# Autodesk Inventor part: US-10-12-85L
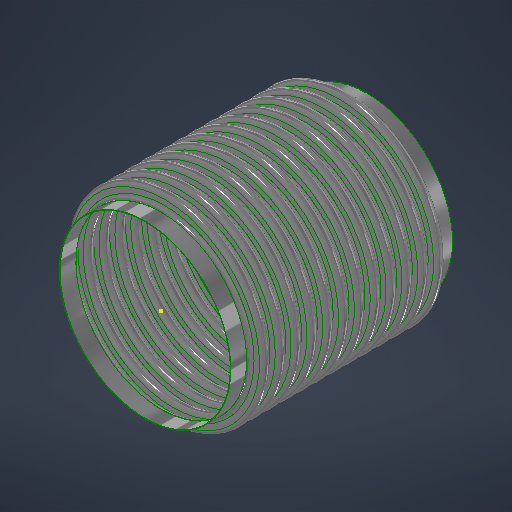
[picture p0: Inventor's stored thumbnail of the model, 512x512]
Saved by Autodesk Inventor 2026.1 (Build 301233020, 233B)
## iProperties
Category: 20 GA (0.036 THICK)
RuleStatus: InUse
Created: 2026-07
Part Number: US-10-12-85L
Project: =STOCK BELLOWS: <Stock Number><SFILL>
Material: ASTM A240-304
Description: =STOCK BELLOWS: <Stock Number>, <SID_> I.D., <SOD_> O.D., <SPLY_> PLY, <Category>, <SNET_CONS> CONS.<PITCH_><STANGENT_> TANGENT<SFILL>
Document SubType Name: Sheet Metal
Designer: LC
Stock Number: U.S-10-12-85L
Surface Area: 659.127 cm^2
Volume: 56.61 cm^3
Sheet Metal Rule: Default
Appearance: STAINLESS STEEL
NET_TUBE: 3.428
COUNTER: 1.500
PBAR: 1.214
PSET: 5.356
PLY: 2
CONS: 2
THK: 0.036
ID: 4.500
OD: 5.500
CONS_: 2
TANGENT: 0.500
PITCH: 0.375
BELLOWS_UPSET: 0.000
NET_CONS: 2
S_CONS: 0
Description_Units: 0
ID_M: 114.30 mm
OD_M: 139.70 mm
THK_M: 0.91 mm
ID_U: 4.500 in
OD_U: 5.500 in
THK_U: 0.036 in
TANGENT2: 0.500
d79: 1.000
d82: 1.000
d83: 26.000
d84: 24.000
d80: 2.571
d81: 10
SID: 2.375
SCONS_: 12
SPITCH: 0.250
SBELLOWS_UPSET: 0.000
SNET_CONS: 12
SS_CONS: 0
SCONS: 8
d174: 8
d177: 0.018
d178: 2.375
d179: 3.000
d180: 0.375
d181: 1.000
d182: 0.000
d190: 8
d191: 1
d192: 1
d193: 8
d194: 0
PART_NUMBER: U.S-10-12-85L
PRESSURE: 85
SIZE: 10.00
STANGENT_: 1.000
d214: 8
d217: 0.030
d218: 6.625
d219: 8.125
d220: 0.500
d221: 1.000
d222: 0.000
d230: 8
d231: 1
d232: 1
d233: 8
d234: 0
STANGENT: 4.000
SPLY_: 1
STHK_: 0.036
SID_: 10.750
SOD_: 12.500
SPITCH_: 1.000
STANGENT__: 1.000
SBELLOWS_UPSET_: 0.000
SDIFF_TAN: 1.000
TAN_TO_TAN: 0.750 in
d252: 2
d275: 2
d287: 0.050
d289: 0.500
d290: 0.000
d263: 2
d265: 1
d268: 2
d269: 0
d286: 2
d288: 1
d291: 2
d292: 0
SOD_NECK: 10 13/16
CFILL: .
SFILL: .
PITCH_: =, <SPITCH_> PITCH,
SREROLL: 0.750
MATTABLE: 20 GA (0.036 THICK)
MESH: ,
CSECT: 2
Author: LC
Keywords: 20 GA (0.036 THICK)
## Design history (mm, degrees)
sketch "Sketch2"
  geometry: L1 (0, -183.595)-(0, 600.956) reference; L2 (58.979, 0)-(57.15, 0); L3 (60.446, -1.467)-(66.554, -1.467); L4 (60.446, -3.296)-(66.554, -3.296); L5 (66.554, -8.058)-(60.446, -8.058); L6 (66.554, -6.229)-(60.446, -6.229); L7 (58.979, -9.525)-(57.15, -9.525); L8 (60.446, 0)-(60.446, -9.525); L9 (66.554, -4.762)-(69.85, -4.763); L10 (57.15, 0)-(57.15, -9.525); L11 (20.376, 102.841)-(20.376, 101.926); L12 (58.262, 488.877)-(58.262, 349.177); L13 (58.262, 479.352)-(58.262, 339.652); L14 (93.133, -58.817)-(93.133, -71.517); L15 (118.746, -66.401)-(118.746, -66.401); L16 (66.554, -6.229)-(66.554, -8.058); L17 (60.446, -6.229)-(60.446, -8.058); L18 (60.446, -7.144)-(66.554, -7.144); L19 (69.85, 0)-(69.85, -9.525); L20 (-66.554, -6.229)-(-66.554, -8.058); L21 (-66.554, -1.467)-(-60.446, -1.467); L22 (-66.554, -3.296)-(-60.446, -3.296); L23 (-60.446, -6.229)-(-66.554, -6.229); L24 (-66.554, -7.144)-(-60.446, -7.144); L25 (-60.446, -8.058)-(-66.554, -8.058); L26 (-60.446, -6.229)-(-60.446, -8.058); L27 (-57.15, -2.522)-(-57.15, -12.047); L28 (-60.446, -4.763)-(-57.15, -4.763); L29 (-66.554, 3.828)-(-66.554, -9.525); L30 (-68.021, 0)-(-69.85, 0); L31 (-69.85, 0)-(-69.85, -9.525); L32 (-68.021, -9.525)-(-69.85, -9.525); A1 r 1.467 centre (60.446, 0) between (58.979, 0) and (60.446, -1.467); A2 r 3.296 centre (60.446, 0) between (57.15, 0) and (60.446, -3.296); A3 r 3.296 centre (66.554, -4.762) between (66.554, -8.058) and (66.554, -1.467); A4 r 1.467 centre (66.554, -4.762) between (66.554, -6.229) and (66.554, -3.296); A5 r 1.467 centre (60.446, -9.525) between (60.446, -8.058) and (58.979, -9.525); A6 r 3.296 centre (60.446, -9.525) between (60.446, -6.229) and (57.15, -9.525); A7 r 2.381 centre (66.554, -4.762) between (66.554, -7.144) and (68.936, -4.762); A8 r 2.381 centre (60.446, -9.525) between (60.446, -7.144) and (58.064, -9.525); A9 r 1.467 centre (-66.554, -9.525) between (-66.554, -8.058) and (-68.021, -9.525); A10 r 1.467 centre (-60.446, -4.763) between (-60.446, -6.229) and (-60.446, -3.296); A11 r 2.381 centre (-60.446, -4.763) between (-60.446, -7.144) and (-58.064, -4.763); A12 r 3.296 centre (-60.446, -4.763) between (-60.446, -8.058) and (-60.446, -1.467); A13 r 2.381 centre (-66.554, -9.525) between (-66.554, -7.144) and (-68.936, -9.525); A14 r 3.296 centre (-66.554, -9.525) between (-66.554, -6.229) and (-69.85, -9.525); A15 r 1.467 centre (-66.554, 0) between (-68.021, 0) and (-66.554, -1.467); A16 r 3.296 centre (-66.554, 0) between (-69.85, 0) and (-66.554, -3.296); 10 further points
  constraints: 62 end point, 38 point on circle, 20 tangent, 16 centre point, 12 parallel, 9 midpoint, 7 vertical, 6 coincident, 6 concentric, 6 point on line, 4 equal radius, 4 perpendicular, 3 horizontal, 1 collinear, 1 horizontal alignment, 10 other
  dimensions: "THK" = 0.9144 distance of L11.start L11.end; "ID" = 114.3 distance of L11.end point (20.376, -12.374); "OD" = 139.7 distance of L12.start L12.end; "PITCH" = 9.525 distance of L12.start L13.start; "TANGENT" = 12.7 distance of L14.start L14.end; "BELLOWS_UPSET" = 0 distance of L15.start L15.end; "d43" = 114.3 diameter of L10 L1 (= ID); "d44" = 139.7 diameter of L9.end L1 (= OD); "d45" = 1.8288 distance between parallel lines of L5 L6 (computed from THK, PLY); "d46" = 3.29565 radius of A3 (computed from PITCH, THK, PLY); "UPSET_PITCH" = 9.525 distance of L2.end L7.end (derived); "SIDEWALL_ANGLE" = 0 deg angle of L3 L9 (derived); "CON_GAP" = 2.9337 distance of point (60.446, -6.229) point (60.446, -3.296) (derived); "TAN1" = 3.74046 dimension on A8 (derived); "TAN2" = 3.74046 dimension on A7 (derived); "LEG1" = 6.1087 distance of L18.start L18.end (derived); "d278" = 1.8288 distance between parallel lines of L25 L23 (derived); "d279" = 3.29565 radius of A12 (derived); "d280" = 9.525 distance of L30.end L31.end (derived); "d281" = 360 deg dimension on L21 L28 (derived); "d282" = 2.9337 distance of point (-66.554, -6.229) point (-66.554, -3.296) (derived); "d283" = 3.74046 dimension on A13 (derived); "d284" = 3.74046 dimension on A11 (derived); "d285" = 6.1087 distance of L24.start L24.end (derived); "d293" = 114.3 diameter of L27 L1 (derived); "d294" = 139.7 diameter of L31 L1 (derived)
  node "Sketch Rectangular Pattern1" dims "d31" = 25.4, "ID" = 114.3
  node "Sketch Rectangular Pattern2" dims "d39" = 25.4, "PITCH" = 9.525
revolve "CONS" stored, may be unused: angle "d48" = 90 deg
node "BELLOW MIDPLANE"
pattern_linear "Rectangular Pattern2" dims "d52" = 9.525 (= UPSET_PITCH)
sketch "Sketch5"
  geometry: C1 r 58.979 at (0, 0) reference; C2 r 57.15 at (0, 0) reference
extrude "TANGENT" new body sketch "Sketch5" distance "d53" = 12.7 (= TANGENT); taper "d54" = 0 deg
revolve "SAMETAN" stored, may be unused: angle "d65" = 90 deg
revolve "DIFFTAN" stored, may be unused: angle "d70" = 90 deg
sketch "Sketch9"
  geometry: L1 (58.391, 0)-(-58.391, 0) reference; L2 (0, -17.78)-(0, 17.78) reference; L3 (41.708, 0)-(-41.708, 0); L4 (41.708, -11.906)-(41.708, 11.906); L5 (29.008, -11.906)-(29.008, 11.906); L6 (15.418, 11.906)-(15.418, -11.906); L7 (-29.008, -11.906)-(-29.008, 11.906); L8 (-41.708, -11.906)-(-41.708, 11.906); L9 (40.914, -11.906)-(40.914, 11.906); L10 (41.708, -11.906)-(40.914, -11.906); L11 (41.708, 11.906)-(40.914, 11.906); L12 (15.815, 11.906)-(15.022, 11.906); L13 (15.022, 11.906)-(15.022, -11.906); L14 (15.022, -11.906)-(15.815, -11.906); L15 (15.815, -11.906)-(15.815, 11.906); L16 (-15.815, 11.906)-(-15.815, -11.906); L17 (-15.418, 11.906)-(-15.418, -11.906); L18 (-15.815, -11.906)-(-15.022, -11.906); L19 (-15.022, -11.906)-(-15.022, 11.906); L20 (-15.022, 11.906)-(-15.815, 11.906); L21 (-41.708, -11.906)-(-40.914, -11.906); L22 (-40.914, -11.906)-(-40.914, 11.906); L23 (-40.914, 11.906)-(-41.708, 11.906); L24 (-41.708, 11.906)-(-41.708, -11.906); L25 (41.708, -0.397)-(-41.708, -0.397); L26 (-41.708, -0.397)-(-41.708, 0.397); L27 (-41.708, 0.397)-(41.708, 0.397); L28 (41.708, 0.397)-(41.708, -0.397); L29 (-41.708, 11.906)-(41.708, 11.906); L30 (41.708, 11.906)-(41.708, 12.7); L31 (41.708, 12.7)-(-41.708, 12.7); L32 (-41.708, 12.7)-(-41.708, 11.906); L33 (41.708, -11.906)-(-41.708, -11.906); L34 (-41.708, -11.906)-(-41.708, -12.7); L35 (-41.708, -12.7)-(41.708, -12.7); L36 (41.708, -12.7)-(41.708, -11.906); 30 further points
  constraints: 68 end point, 13 midpoint, 13 parallel, 8 horizontal, 7 perpendicular, 6 equal length, 3 point on line, 2 vertical, 14 other
  dimensions: "d115" = 23.8125 distance of L4.start L4.end (derived); "d116" = 12.7 distance between parallel lines of L4 L5 (derived); "d117" = 13.58962 distance between parallel lines of L5 L6 (derived); "d125" = 44.42645 distance between parallel lines of L7 L6 (derived); "d127" = 12.7 distance between parallel lines of L8 L7 (derived); "d128" = 26.28962 distance between parallel lines of L6 L4 (derived); "d130" = 83.41607 distance between parallel lines of L8 L4 (derived); "RULER_THK" = 0.79375 distance between parallel lines of L4 L9; "d135" = 0.79375 distance of L13.end L14.end (derived); "d138" = 30.83684 distance of L13.end L16.end (derived); "d143" = 0.79375 distance of L22.end L8.end (derived); "d144" = 0.79375 distance between parallel lines of L27 L25 (derived)
extrude "RULER" join sketch "Sketch9" distance "d149" = 0.79375 (derived); taper "d150" = 0 deg
extrude "BARS" join sketch "Sketch9" distance "d151" = 0.79375 (derived); taper "d152" = 0 deg
pattern_linear "Rectangular Pattern4" dims "d155" = 30.83684 (derived)
sketch "Sketch13"
  geometry: L1 (93.149, -52.467)-(93.149, -77.867); L2 (137.439, 0)-(136.525, 0); L3 (137.439, -25.4)-(136.525, -25.4); L4 (151.943, -19.507)-(143.332, -19.507); L5 (151.943, -18.593)-(143.332, -18.593); L6 (151.943, -12.7)-(158.75, -12.7); L7 (143.332, -5.893)-(151.943, -5.893); L8 (143.332, 0)-(143.332, -25.4); L9 (136.525, 0)-(136.525, -25.4); L10 (58.254, -287.939)-(58.254, -605.439); L11 (58.254, -313.339)-(58.254, -630.839); L12 (58.254, -364.139)-(58.254, -681.639); L13 (58.254, -389.539)-(58.254, -707.039); L14 (58.254, -414.939)-(58.254, -732.439); L15 (58.254, -440.339)-(58.254, -757.839); L16 (58.254, -465.739)-(58.254, -783.239); L17 (58.254, -338.739)-(58.254, -656.239); L18 (20.376, 102.841)-(20.376, 101.926); L19 (143.332, -6.807)-(151.943, -6.807); L20 (0, -810.565)-(0, 254.897) reference; L21 (-25.718, 0)-(154.305, 0) reference; A1 r 5.893 centre (143.332, 0) between (137.439, 0) and (143.332, -5.893); A2 r 5.893 centre (143.332, -25.4) between (143.332, -19.507) and (137.439, -25.4); A3 r 6.807 centre (143.332, -25.4) between (143.332, -18.593) and (136.525, -25.4); A4 r 5.893 centre (151.943, -12.7) between (151.943, -18.593) and (151.943, -6.807); A5 r 6.807 centre (151.943, -12.7) between (151.943, -19.507) and (151.943, -5.893); A6 r 6.807 centre (143.332, 0) between (136.525, 0) and (143.332, -6.807); 6 further points; 1 other entity
  constraints: 38 end point, 15 point on circle, 9 tangent, 6 centre point, 6 parallel, 5 vertical alignment, 4 point on line, 4 vertical, 3 coincident, 3 concentric, 2 collinear, 2 equal radius, 1 horizontal, 1 perpendicular, 23 other
  dimensions: "SBELLOWS_UPSET_" = 0 distance of point (118.762, -66.401) point (118.762, -66.401); "STOTAL_THK_BELLOW__" = 0.9144 distance between parallel lines of L4 L5 (derived); "d224" = 6.8072 radius of A5 (derived); "d225" = 25.4 distance of L2.end L3.end (derived); "SSIDEWALL_ANGLE_" = 0 deg angle of L7 L6 (derived); "SSCON_GAP_" = 11.7856 distance of point (143.332, -18.593) point (143.332, -6.807) (derived); "d235" = 273.05 diameter of L9 L20 (derived); "d236" = 317.5 diameter of L6.end L20 (derived)
  node "Sketch Rectangular Pattern4" dims "d228" = 25.4
  node "Sketch Rectangular Pattern5" dims "d229" = 25.4
revolve "SBELLOW" stored, may be unused: angle "d197" = 90 deg
pattern_linear "Rectangular Pattern5" dims "d204" = 25.4 (derived)
revolve "STANGENT" stored, may be unused: angle "d240" = 90 deg
revolve "SSAMETAN" stored, may be unused: angle "d241" = 90 deg
revolve "SDIFFTAN" stored, may be unused: angle "d246" = 90 deg
revolve "INVCON" stored, may be unused: angle "d295" = 90 deg
pattern_linear "Rectangular Pattern6" dims "d298" = 9.525 (derived)
revolve "INVTANGENT" stored, may be unused: angle "d302" = 90 deg
revolve "INVSAMETAN" stored, may be unused: angle "d307" = 90 deg
revolve "INVDIFFTAN" stored, may be unused: angle "d312" = 90 deg
sketch "ID BELLOW MOUNT CALC"
  geometry: L1 (44.45, 0)-(38.1, 0); L2 (38.1, 0)-(38.1, 12.7); L3 (38.1, 12.7)-(44.45, 12.7); L4 (44.45, 12.7)-(44.45, 0); L5 (36.513, 12.7)-(34.684, 12.7); L6 (34.684, 12.7)-(34.684, 0); L7 (34.684, 0)-(36.513, 0); L8 (36.513, 0)-(36.513, 12.7); L9 (0, -2.54)-(0, 15.24) reference; L10 (-8.89, 0)-(53.34, 0) reference; 1 further point
  constraints: 16 end point, 5 parallel, 2 collinear, 2 horizontal, 2 perpendicular
  dimensions: "d314" = 12.7 distance of L5.end L6.end (derived); "d315" = 1.8288 distance of L5.start L5.end (derived); "IG" = 1.5875 distance between parallel lines of L2 L8; "PIPE_OD" = 88.9 diameter of L4 L9; "PIPE_WALL" = 6.35 distance of L2.end L3.end; "ID_MT_BELLOW" = 69.3674 diameter of L6 L9 (derived)
revolve "CFILL" stored, may be unused: angle "d320" = 90 deg
pattern_linear "Rectangular Pattern7" dims "d323" = 9.525 (derived)
revolve "SFILL" stored, may be unused: angle "d324" = 90 deg
pattern_linear "Rectangular Pattern8" dims "d327" = 25.4 (derived)
node "STOCK BELLOW MIDPLANE"
sketch "Sketch21"
  geometry: L1 (0, -222.25)-(0, 222.25) reference; L2 (-222.25, 0)-(222.25, 0) reference; L3 (-0.099, 71.437)-(0.099, 71.437); L4 (0.099, 71.437)-(0.099, 55.562); L5 (0.099, 55.562)-(-0.099, 55.562); L6 (-0.099, 55.562)-(-0.099, 71.437); C1 r 55.562 at (0, 0); C2 r 71.437 at (0, 0); 3 further points
  constraints: 8 end point, 2 centre point, 2 coincident, 2 parallel, 2 tangent, 1 horizontal, 1 perpendicular, 1 other
  dimensions: "d329" = 111.125 diameter of C1 (derived); "d330" = 142.875 diameter of C2 (derived); "d331" = 0.19844 distance of L3.start L3.end
extrude "CLAMSHELL" cut sketch "Sketch21" extent not by distance; stored distance "d332" = 0; taper "d333" = 0 deg
pattern_circular "Circular Pattern1" dims angle "d335" = 180 deg (derived)
node "BELLOW"
sketch "Sketch6"
  geometry: L1 (-19.05, 58.979)-(-6.35, 58.979); L2 (-6.35, 58.979)-(-6.35, 57.15); L3 (-6.35, 57.15)-(-19.05, 57.15); L4 (-19.05, 57.15)-(-19.05, 58.979); L5 (2.54, 0)-(-59.69, 0) reference; L6 (-38.1, -108.388)-(-38.1, 156.601) reference; 1 further point
  constraints: 8 end point, 2 parallel, 1 horizontal, 1 perpendicular
  dimensions: "d61" = 12.7 distance of L2.end L3.end (derived); "d62" = 1.8288 distance of L1.end L2.end (derived); "d63" = 114.3 diameter of L3 L5 (derived); "d64" = 19.05 distance between parallel lines of L4 L6 (derived)
sketch "Sketch12"
  geometry: 1 further point
sketch "Sketch14"
  geometry: L1 (-25.4, 137.439)-(0, 137.439); L2 (0, 137.439)-(0, 136.525); L3 (0, 136.525)-(-25.4, 136.525); L4 (-25.4, 136.525)-(-25.4, 137.439); L5 (5.08, 0)-(-30.48, 0) reference; L6 (0, -22.06)-(0, 132.359) reference; 1 further point
  constraints: 8 end point, 2 parallel, 1 collinear, 1 horizontal, 1 perpendicular
  dimensions: "d237" = 0.9144 distance of L3.end L1.start (derived); "d238" = 273.05 diameter of L3 L5 (derived); "d239" = 25.4 distance of L1.start L1.end (derived); "SOD_NECK" = 274.8788 diameter of L1 L5 (derived)
sketch "Sketch15"
  geometry: L1 (-22.06, 0)-(132.359, 0) reference; L2 (136.525, -304.8)-(137.439, -304.8); L3 (137.439, -304.8)-(137.439, -330.2); L4 (137.439, -330.2)-(136.525, -330.2); L5 (136.525, -330.2)-(136.525, -304.8); L6 (0, -215.9)-(0, 50.8) reference; 1 further point
  constraints: 8 end point, 2 parallel, 1 horizontal, 1 perpendicular
  dimensions: "d205" = 25.4 distance of L4.end L2.start (derived); "d206" = 0.9144 distance of L3.end L4.end (derived); "d207" = 273.05 diameter of L5 L6 (derived); "d208" = 304.8 distance between parallel lines of L1 L2 (derived)
node "TANGENT_"
node "SAME_TAN"
sketch "Sketch8"
  geometry: L1 (58.979, -19.05)-(57.15, -19.05); L2 (57.15, -19.05)-(57.15, -31.75); L3 (57.15, -31.75)-(58.979, -31.75); L4 (58.979, -31.75)-(58.979, -19.05); L5 (0, -40.64)-(0, 21.59) reference; L6 (-108.388, 0)-(156.601, 0) reference; 1 further point
  constraints: 8 end point, 2 parallel, 1 horizontal, 1 perpendicular
  dimensions: "d66" = 114.3 diameter of L2 L5 (derived); "TOTAL_THK_BELLOW" = 1.8288 distance of L2.end L3.end (derived); "d68" = 19.05 distance between parallel lines of L1 L6 (derived); "d69" = 12.7 distance of L1.end L2.end (derived)
node "DIFF_TAN"
node "Sketch Rectangular Pattern3" dims "d138" = 30.83684 (derived), "d141" = 25.4
node "SBELLOW_"
node "STANGENT_"
node "SSAME_TAN"
sketch "Sketch16"
  geometry: L1 (137.439, -304.8)-(136.525, -304.8); L2 (136.525, -304.8)-(136.525, -330.2); L3 (136.525, -330.2)-(137.439, -330.2); L4 (137.439, -330.2)-(137.439, -304.8); L5 (0, -215.9)-(0, 50.8) reference; L6 (-22.06, 0)-(132.359, 0) reference; 1 further point
  constraints: 8 end point, 2 parallel, 1 horizontal, 1 perpendicular
  dimensions: "SDIFF_TAN" = 25.4 distance of L3.end L1.start; "d243" = 0.9144 distance of L2.end L3.end (derived); "d244" = 304.8 distance between parallel lines of L1 L6 (derived); "d245" = 273.05 diameter of L2 L5 (derived)
node "SDIFF_TAN"
body "Solid15"
sketch "Sketch17"
  geometry: L1 (69.85, 12.7)-(68.021, 12.7); L2 (68.021, 12.7)-(68.021, 0); L3 (68.021, 0)-(69.85, 0); L4 (69.85, 0)-(69.85, 12.7); L5 (0, -2.54)-(0, 15.24) reference; L6 (-13.97, 0)-(83.82, 0) reference; 2 further points
  constraints: 8 end point, 2 parallel, 1 horizontal, 1 midpoint, 1 perpendicular, 1 point on line
  dimensions: "INVTANGENT" = 12.7 distance of L3.end L1.start (derived); "d300" = 1.8288 distance of L1.start L1.end (derived); "d301" = 139.7 diameter of L4 L5 (derived)
body "Solid16"
sketch "Sketch18"
  geometry: L1 (69.85, -19.05)-(68.021, -19.05); L2 (68.021, -19.05)-(68.021, -31.75); L3 (68.021, -31.75)-(69.85, -31.75); L4 (69.85, -31.75)-(69.85, -19.05); L5 (-13.97, 0)-(83.82, 0) reference; L6 (0, -40.64)-(0, 21.59) reference; 1 further point
  constraints: 8 end point, 2 parallel, 1 horizontal, 1 perpendicular
  dimensions: "d303" = 19.05 distance between parallel lines of L1 L5 (derived); "d304" = 12.7 distance of L3.end L1.start (derived); "d305" = 1.8288 distance of L2.end L3.end (derived); "d306" = 139.7 diameter of L4 L6 (derived)
body "Solid17"
sketch "Sketch19"
  geometry: L1 (69.85, -19.05)-(68.021, -19.05); L2 (68.021, -19.05)-(68.021, -31.75); L3 (68.021, -31.75)-(69.85, -31.75); L4 (69.85, -31.75)-(69.85, -19.05); L5 (0, -40.64)-(0, 21.59) reference; L6 (-13.97, 0)-(83.82, 0) reference; 1 further point
  constraints: 8 end point, 2 parallel, 1 horizontal, 1 perpendicular
  dimensions: "d308" = 12.7 distance of L1.end L2.end (derived); "d309" = 139.7 diameter of L4 L5 (derived); "d310" = 1.8288 distance of L2.end L3.end (derived); "d311" = 19.05 distance between parallel lines of L1 L6 (derived)
body "Solid18"
body "Solid19"
body "Solid20"
other parameters: "BMPL" = -152.4, "PSET" = 136.0424 (computed from OD, THK, PLY) [user parameter], "PBAR" = 30.83684 (= 0.570796 x PITCH + OD - ID) [user parameter; used in 1 equation term], "COUNTER" = 15 [user parameter], "NET_TUBE" = 87.07367 (computed from CONS_, PBAR, TANGENT) [user parameter], "S_CONS" = 0 [user parameter; used in 1 equation term], "ID_M" = 114.3 (= ID) [user parameter], "OD_M" = 139.7 (= OD) [user parameter], "THK_M" = 0.9144 (= THK) [user parameter], "ID_U" = 114.3 (= ID) [user parameter], "OD_U" = 139.7 (= OD) [user parameter], "THK_U" = 0.9144 (= THK) [user parameter], "D_UNITS" = 0 [user parameter], "TANGENT2" = 12.7 [user parameter], "TAN_TO_TAN" = 19.05 [user parameter], "OD_NECK" = 117.9576 [user parameter], "d79" = 25.4, "d80" = 65.29823 [user parameter], "d82" = 25.4, "d83" = 660.4, "d84" = 609.6, "sa_0" = 4, "FRAME_THK" = 0.79375 [user parameter], "CON_FLAT" = 13.58962 [user parameter], "SID" = 60.325 [user parameter], "SPITCH" = 6.35 [user parameter], "STANGENT_" = 25.4 [user parameter], "SBELLOWS_UPSET" = 0 [user parameter], "SS_CONS" = 0 [user parameter], "STAN_TO_TAN_" = 304.8 [user parameter], "d100" = 0.9144 [user parameter], "d191" = 25.4 [user parameter], "d194" = 0 [user parameter], "STANGENT" = 101.6 [user parameter], "d234" = 0 [user parameter], "SUPSET_PITCH_" = 25.4 [user parameter], "d269" = 0 [user parameter], "d287" = 1.27, "d289" = 12.7, "d290" = 0, "d292" = 0 [user parameter], "Thickness" = 3.048 (derived), "KFactor" = 4.4, "BendRadius" = 3.048 (derived), "BendReliefWidth" = 3.048 (derived), "BendReliefDepth" = 1.524 (derived), "CornerReliefSize" = 12.192 (derived), "SeamGap" = 0.00508, "MinimumRemnant" = 6.096 (derived), "TransitionRadius" = 3.048 (derived), "JacobiRadiusSize" = 3.048 (derived), "GapSize" = 3.048 (derived), "SREROLL" = 19.05 [user parameter], "CUR_STK_PITCH" = 25.4 [user parameter], "d328" = -152.4 (derived), "CSECTDEG" = 180 deg [user parameter]
